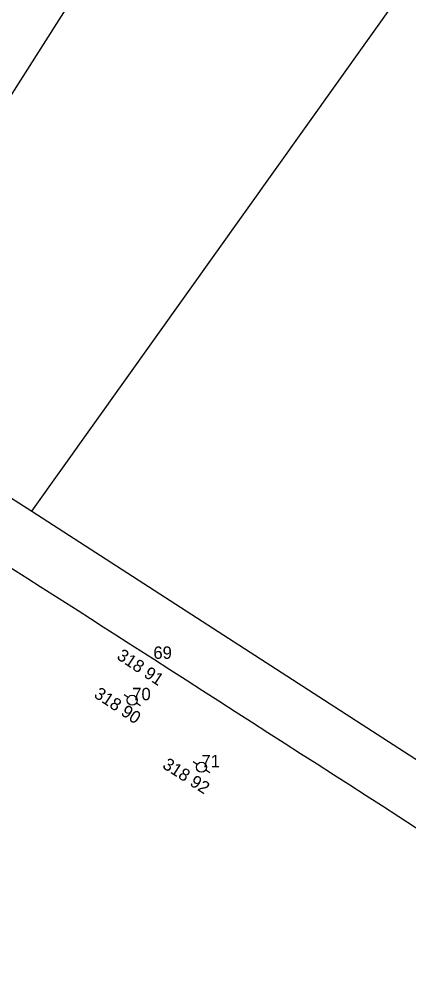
# Model space of a CAD drawing. Extents: x -742884 to -742543, y -1054677 to -1054433.
# Drawn here: x -742664.25 to -742654.84, y -1054523.59 to -1054500.54 of the extents above; entities that cross this region are included whole.
import ezdxf

# ---------------------------------------------------------------- set-up
doc = ezdxf.new("R2010")
doc.units = 0
for name, color, linetype in [('Vrstva 1', 7, 'Continuous'), ('Vrstva 11', 7, 'Continuous'), ('Vrstva 2', 7, 'Continuous'), ('Vrstva 3', 7, 'Continuous'), ('Vrstva 4', 7, 'Continuous'), ('Vrstva 50', 7, 'Continuous'), ('Vrstva 8', 7, 'Continuous')]:
    doc.layers.add(name, color=color, linetype=linetype)

msp = doc.modelspace()

# ---------------------------------------------------------------- linework, layer by layer
at = {"layer": 'Vrstva 1'}
for p, q in [((-742661.01, -1054516), (-742661.01, -1054516)), ((-742661.52, -1054517), (-742661.52, -1054517)), ((-742659.85, -1054518.62), (-742659.85, -1054518.62))]:
    msp.add_line(p, q, dxfattribs=at)
at = {"layer": 'Vrstva 11'}
msp.add_spline([(-742641.45, -1054542), (-742646.08, -1054542.32), (-742650.28, -1054545.1), (-742653.63, -1054549.14), (-742658.66, -1054557.13), (-742664.13, -1054565.84), (-742667.81, -1054569.62), (-742669.76, -1054570.07), (-742674.4, -1054567.88), (-742684.66, -1054562.03), (-742693.02, -1054556.88), (-742694.43, -1054554.37), (-742693.99, -1054552.67), (-742684.52, -1054539.64), (-742677.51, -1054529.95), (-742676.26, -1054526.54), (-742677.27, -1054522.39), (-742681.19, -1054517.29), (-742689.28, -1054510.73), (-742697.86, -1054505.14), (-742704.02, -1054502.75), (-742713.11, -1054501.07), (-742723.98, -1054503.51), (-742736.77, -1054510.1), (-742745.39, -1054515.75), (-742752.81, -1054521.82), (-742762.72, -1054531.38), (-742770.54, -1054539.36), (-742775.54, -1054544.64)], degree=3, dxfattribs=at)
at = {"layer": 'Vrstva 4'}
msp.add_spline([(-742718.8, -1054478.84), (-742709.4, -1054484.88), (-742695.99, -1054493.43), (-742680.4, -1054503.55), (-742661.01, -1054516), (-742635.78, -1054532.31)], degree=3, dxfattribs=at)
at = {"layer": 'Vrstva 50'}
for p, q in [((-742663.94, -1054512.43), (-742645.368, -1054486.322)), ((-742680.73, -1054501.69), (-742663.94, -1054512.43)), ((-742663.94, -1054512.43), (-742647.17, -1054523.29))]:
    msp.add_line(p, q, dxfattribs=at)
msp.add_lwpolyline([(-742657.61, -1054484.93), (-742655.81, -1054482.15), (-742660.56, -1054479.21), (-742665.7, -1054487.1), (-742666.25, -1054486.74), (-742674.65, -1054499.83), (-742666.22, -1054505.17), (-742661.11, -1054497.12), (-742664.22, -1054495.12), (-742657.61, -1054484.93)], dxfattribs=at)
at = {"layer": 'Vrstva 8'}
for p, q in [((-742661.621, -1054516.934), (-742661.717, -1054516.871)), ((-742661.319, -1054517.132), (-742661.418, -1054517.067)), ((-742659.951, -1054518.554), (-742660.047, -1054518.491)), ((-742659.649, -1054518.752), (-742659.748, -1054518.687))]:
    msp.add_line(p, q, dxfattribs=at)
for centre in [(-742661.52, -1054517), (-742659.85, -1054518.62)]:
    msp.add_circle(centre, 0.121, dxfattribs=at)

# ---------------------------------------------------------------- texts
at = {"layer": 'Vrstva 2'}
for s, p in [('69', (-742661.01, -1054516)), ('70', (-742661.52, -1054517)), ('71', (-742659.85, -1054518.62))]:
    msp.add_text(s, height=0.3, dxfattribs=at).set_placement(p)
at = {"layer": 'Vrstva 3'}
for s, rotation, p in [('318 91 ', 326.5385, (-742661.914, -1054515.987)), ('318 90 ', 326.5674, (-742662.466, -1054516.912)), ('318 92 ', 327.5966, (-742660.812, -1054518.625))]:
    msp.add_text(s, height=0.3, rotation=rotation, dxfattribs=at).set_placement(p)

doc.saveas('drawing.dxf')
